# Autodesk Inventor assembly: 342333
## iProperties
Company: Mayer & Müller AG Schaltgeräte
Created: 2006-10
Part Number: 342333
Document SubType Name: Assembly
Designer: I.Baliuc
Manufacturer: Standard
Standards Organization: Custom
Description: Spule, kpl.
Mass: 1824.96 g
Surface Area: 2621.68 cm^2
Volume: 221.817 cm^3
Density: 8.2273 g/cm^3
dX*dY*dZ: 80mm x 83mm x 85mm
Flaeche: 257810 mm²
Volumen: 231215 mm³
Author: T.Messerschmitt
Revision Number: 342333
